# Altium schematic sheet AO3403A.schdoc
size 127 x 101 mm
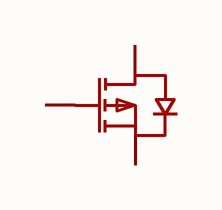
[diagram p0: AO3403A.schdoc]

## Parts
Q?  ao3403a  [SOT-23-3_L2.9-W1.3-P1.90-LS2.4-BR]  (value not drawn)

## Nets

Not connected (* = marked no-connect by the designer): Q? 1(G) 2(S) 3(D)

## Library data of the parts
Q? = ao3403a: 数量:1个P沟道;漏源电压(Vdss):30V;连续漏极电流(Id):2.6A;导通电阻(RDS(on)):88mΩ@10V；103mΩ@4.5V;耗散功率(Pd):1.4W;阈值电压(Vgs(th)):1V;; Manufacturer: UMW(友台半导体); AddInBom: yes; ModelId: c62791f0466c4ae2a892c056b845b0ca; ModelName: SOT-23-3P_L2.9-W1.3-H1.0-LS2.4-P0.95; ModelTransform: 98.425,114.173,0,180,0,0,0.0005,-0.0005,0; Number: 1个P沟道; Drain to Source Voltage: 30V; Current - Continuous Drain(Id): 2.6A; Pd - Power Dissipation: 1.4W; Gate Threshold Voltage (Vgs(th)): 1V; Gate Charge(Qg): 5.9nC@10V; Input Capacitance(Ciss): 260pF; Reverse Transfer Capacitance (Crss@Vds): 20pF; Output Capacitance(Coss): 37pF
